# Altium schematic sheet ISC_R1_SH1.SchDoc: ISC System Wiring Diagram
size C; DrawnBy: Filiberto Clara; Engineer: Filiberto Clara; Organization: LIGO Laboratory; Address1: California Institute of Technology; Address2: Massachusetts Institute of Technology; SheetNumber: 10; SheetTotal: 39
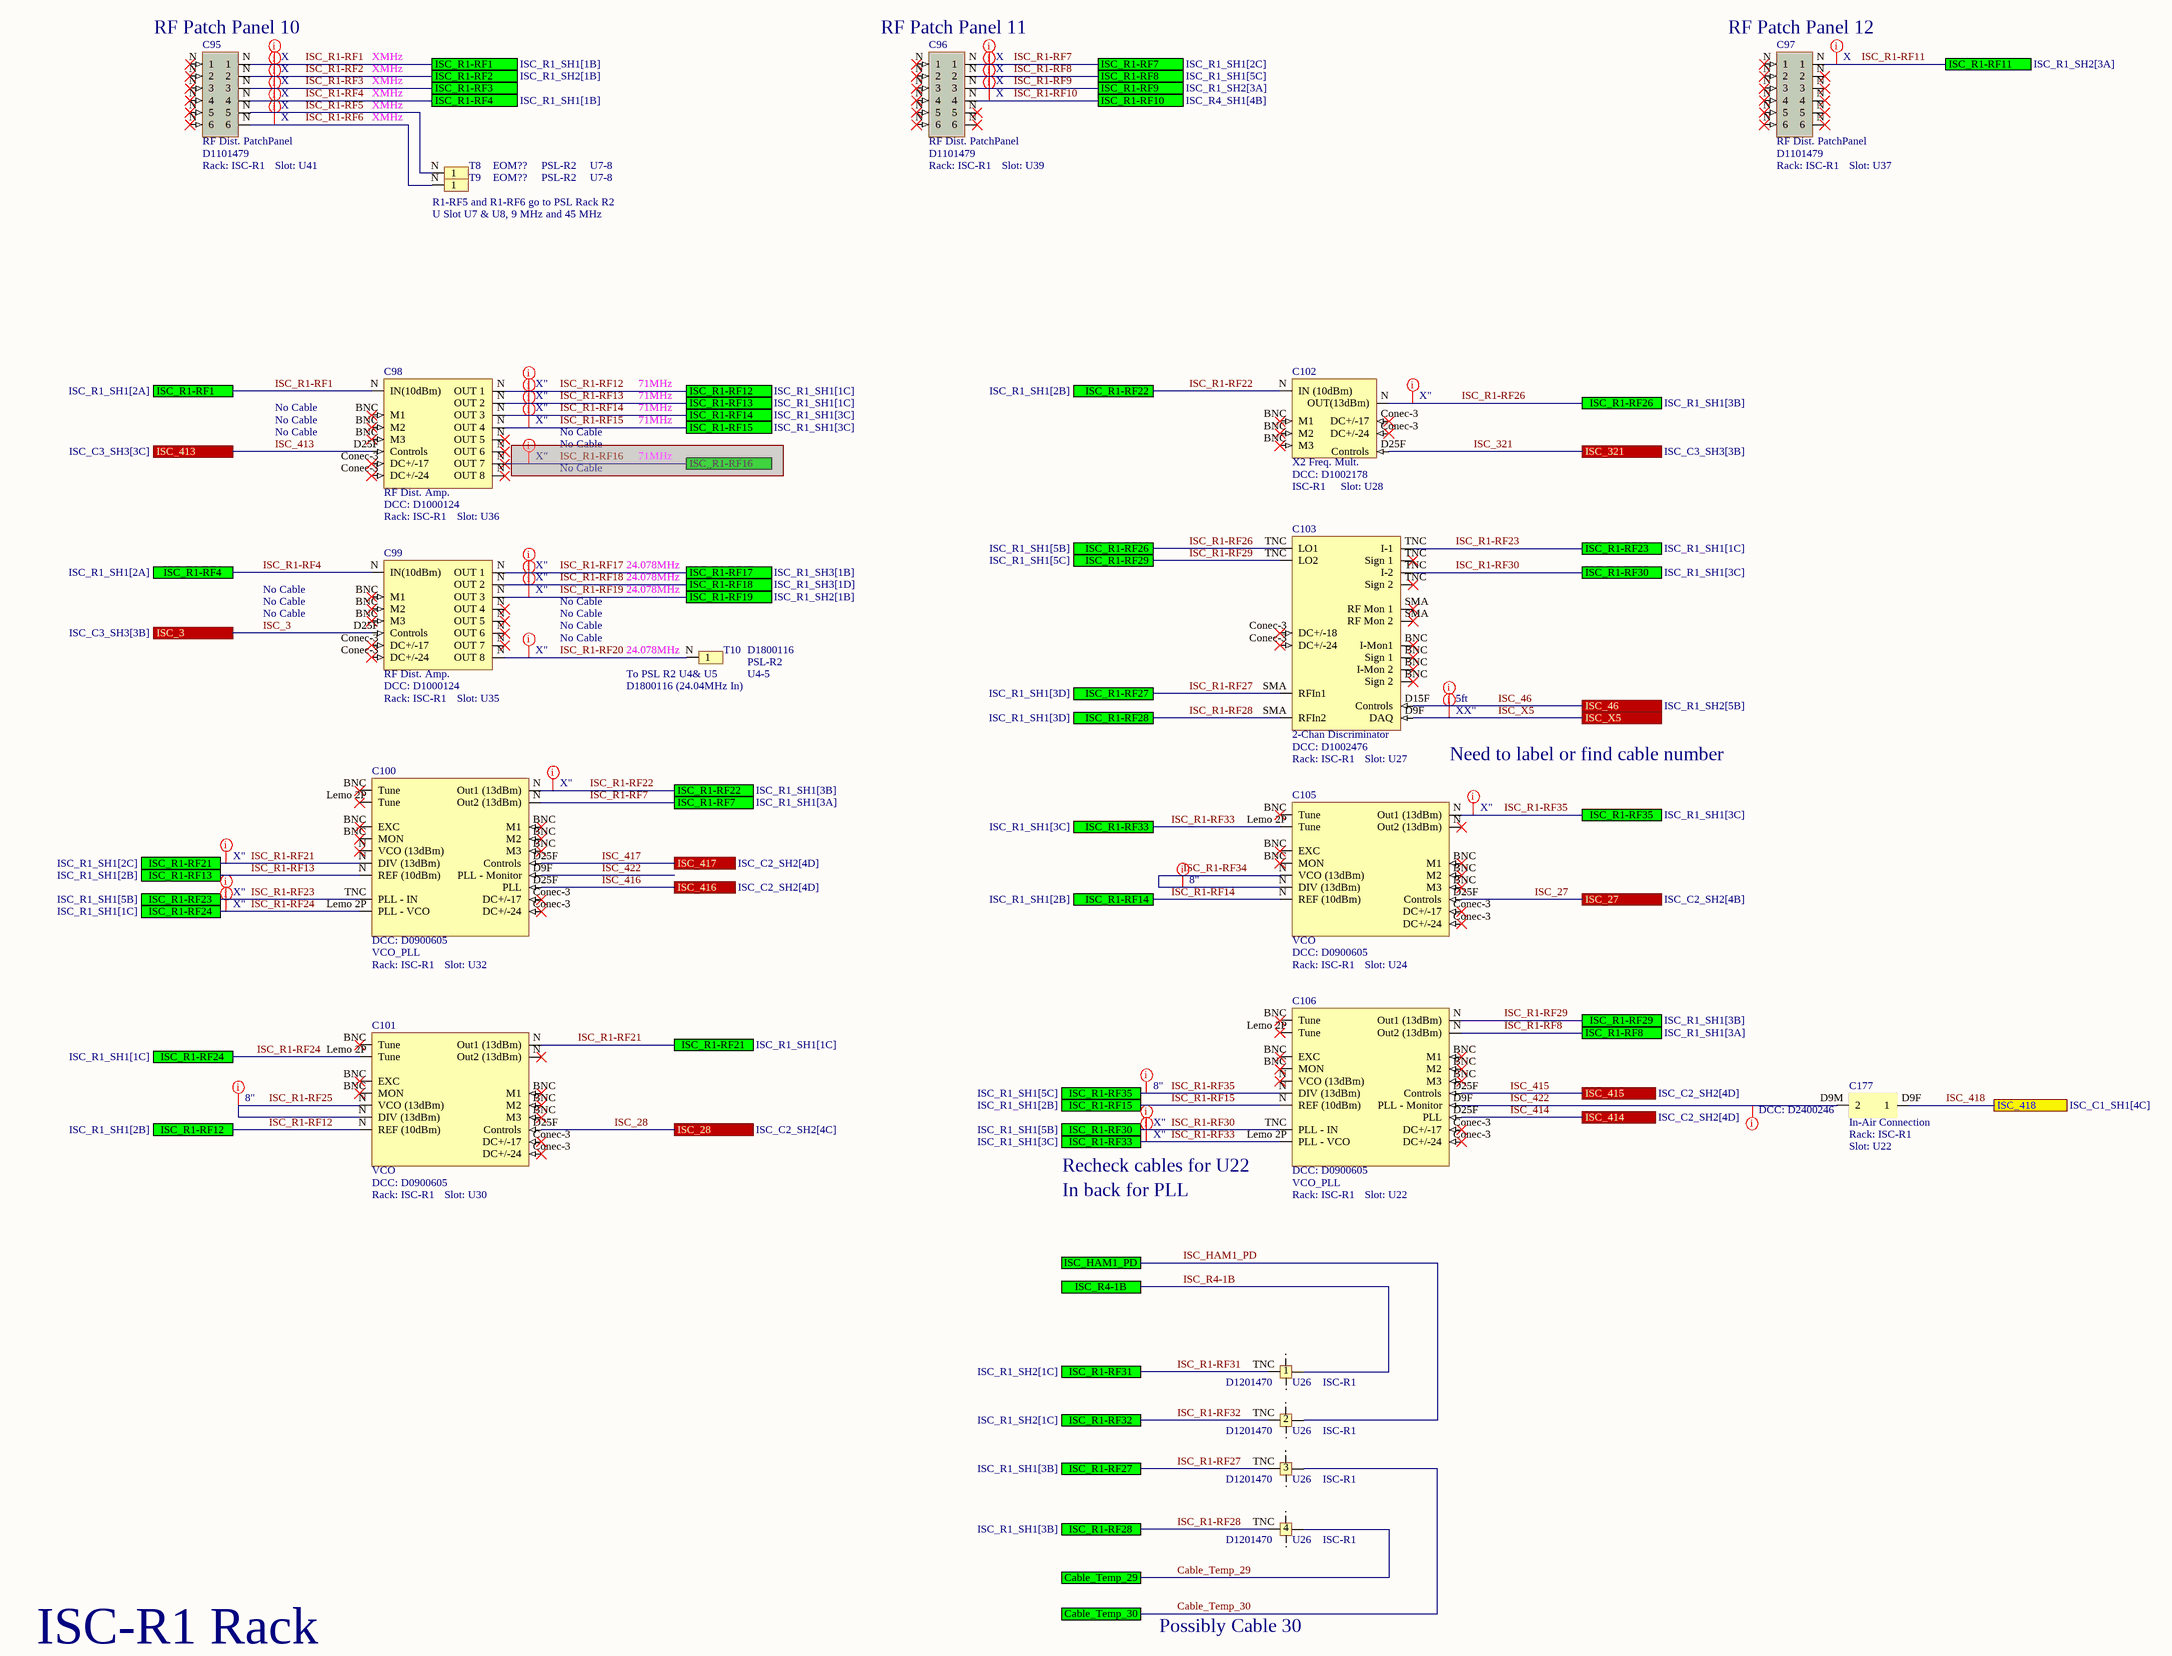
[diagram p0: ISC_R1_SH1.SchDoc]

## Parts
C95  RF Dist. PatchPanel  DCC: D1101479  Rack: ISC-R1  Slot: U41
C96  RF Dist. PatchPanel  DCC: D1101479  Rack: ISC-R1  Slot: U39
C97  RF Dist. PatchPanel  DCC: D1101479  Rack: ISC-R1  Slot: U37
C98  RF Dist. Amp.  DCC: D1000124  Rack: ISC-R1  Slot: U36
C99  RF Dist. Amp.  DCC: D1000124  Rack: ISC-R1  Slot: U35
C100  VCO_PLL  DCC: D0900605  Rack: ISC-R1  Slot: U32
C101  VCO  DCC: D0900605  Rack: ISC-R1  Slot: U30
C102  X2 Freq. Mult.  DCC: D1002178  Rack: ISC-R1  Slot: U28
C103  2-Chan Discriminator  DCC: D1002476  Rack: ISC-R1  Slot: U27
C104  DCC: D1201470  Rack: ISC-R1  Slot: U26  (hidden comment: Patch Panel TNC 1U)  (parts A,B,C,D of 4)
C105  VCO  DCC: D0900605  Rack: ISC-R1  Slot: U24
C106  VCO_PLL  DCC: D0900605  Rack: ISC-R1  Slot: U22
C177  In-Air Connection  Rack: ISC-R1  Slot: U22
T8  EOM??  Rack: PSL-R2  Slot: U7-8
T9  EOM??  Rack: PSL-R2  Slot: U7-8
T10  D1800116  Rack: PSL-R2  Slot: U4-5

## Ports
Cable_Temp_29, Cable_Temp_30, ISC_3 (see ISC_C3_SH3[3B]), ISC_27 (see ISC_C2_SH2[4B]), ISC_28 (see ISC_C2_SH2[4C]), ISC_46 (see ISC_R1_SH2[5B]), ISC_321 (see ISC_C3_SH3[3B]), ISC_413 (see ISC_C3_SH3[3C]), ISC_414 (see ISC_C2_SH2[4D]), ISC_415 (see ISC_C2_SH2[4D]), ISC_416 (see ISC_C2_SH2[4D]), ISC_417 (see ISC_C2_SH2[4D]), ISC_418 (see ISC_C1_SH1[4C]), ISC_HAM1_PD, ISC_R1-RF1 (see ISC_R1_SH1[1B]), ISC_R1-RF1 (see ISC_R1_SH1[2A]), ISC_R1-RF2 (see ISC_R1_SH2[1B]), ISC_R1-RF3, ISC_R1-RF4 (see ISC_R1_SH1[1B]), ISC_R1-RF4 (see ISC_R1_SH1[2A]), ISC_R1-RF7 (see ISC_R1_SH1[2C]), ISC_R1-RF7 (see ISC_R1_SH1[3A]), ISC_R1-RF8 (see ISC_R1_SH1[3A]), ISC_R1-RF8 (see ISC_R1_SH1[5C]), ISC_R1-RF9 (see ISC_R1_SH2[3A]), ISC_R1-RF10 (see ISC_R4_SH1[4B]), ISC_R1-RF11 (see ISC_R1_SH2[3A]), ISC_R1-RF12 (see ISC_R1_SH1[1C]), ISC_R1-RF12 (see ISC_R1_SH1[2B]), ISC_R1-RF13 (see ISC_R1_SH1[1C]), ISC_R1-RF13 (see ISC_R1_SH1[2B]), ISC_R1-RF14 (see ISC_R1_SH1[2B]), ISC_R1-RF14 (see ISC_R1_SH1[3C]), ISC_R1-RF15 (see ISC_R1_SH1[2B]), ISC_R1-RF15 (see ISC_R1_SH1[3C]), ISC_R1-RF16, ISC_R1-RF17 (see ISC_R1_SH3[1B]), ISC_R1-RF18 (see ISC_R1_SH3[1D]), ISC_R1-RF19 (see ISC_R1_SH2[1B]), ISC_R1-RF21 (see ISC_R1_SH1[1C]), ISC_R1-RF21 (see ISC_R1_SH1[2C]), ISC_R1-RF22 (see ISC_R1_SH1[2B]), ISC_R1-RF22 (see ISC_R1_SH1[3B]), ISC_R1-RF23 (see ISC_R1_SH1[1C]), ISC_R1-RF23 (see ISC_R1_SH1[5B]), ISC_R1-RF24 (see ISC_R1_SH1[1C]), ISC_R1-RF26 (see ISC_R1_SH1[3B]), ISC_R1-RF26 (see ISC_R1_SH1[5B]), ISC_R1-RF27 (see ISC_R1_SH1[3B]), ISC_R1-RF27 (see ISC_R1_SH1[3D]), ISC_R1-RF28 (see ISC_R1_SH1[3B]), ISC_R1-RF28 (see ISC_R1_SH1[3D]), ISC_R1-RF29 (see ISC_R1_SH1[3B]), ISC_R1-RF29 (see ISC_R1_SH1[5C]), ISC_R1-RF30 (see ISC_R1_SH1[3C]), ISC_R1-RF30 (see ISC_R1_SH1[5B]), ISC_R1-RF31 (see ISC_R1_SH2[1C]), ISC_R1-RF32 (see ISC_R1_SH2[1C]), ISC_R1-RF33 (see ISC_R1_SH1[3C]), ISC_R1-RF35 (see ISC_R1_SH1[3C]), ISC_R1-RF35 (see ISC_R1_SH1[5C]), ISC_R4-1B, ISC_X5

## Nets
Cable_Temp_29: C104.TNC ; port Cable_Temp_29
Cable_Temp_30: C104.TNC ; port Cable_Temp_30
ISC_3: C99.D25F(Controls) ; port ISC_3
ISC_27: C105.D25F(Controls) ; port ISC_27
ISC_28: C101.D25F(Controls) ; port ISC_28
ISC_46: C103.D15F(Controls) ; port ISC_46
ISC_321: C102.D25F(Controls) ; port ISC_321
ISC_413: C98.D25F(Controls) ; port ISC_413
ISC_414: C106.D25F(PLL) ; port ISC_414
ISC_415: C106.D25F(Controls) ; port ISC_415
ISC_416: C100.D25F(PLL) ; port ISC_416
ISC_417: C100.D25F(Controls) ; port ISC_417
ISC_418: C177.D9F(1) ; port ISC_418
ISC_422: C100.D9F(PLL_-_Monitor) C106.D9F(PLL_-_Monitor) C177.D9M(2)
ISC_HAM1_PD: C104.TNC ; port ISC_HAM1_PD
ISC_R1-RF1: C95.N(1) C98.N(IN(10dBm)) ; port ISC_R1-RF1
ISC_R1-RF2: C95.N(2) ; port ISC_R1-RF2
ISC_R1-RF3: C95.N(3) ; port ISC_R1-RF3
ISC_R1-RF4: C95.N(4) C99.N(IN(10dBm)) ; port ISC_R1-RF4
ISC_R1-RF5: C95.N(5) T8.N(1)
ISC_R1-RF6: C95.N(6) T9.N(1)
ISC_R1-RF7: C96.N(1) C100.N(Out2_(13dBm)) ; port ISC_R1-RF7
ISC_R1-RF8: C96.N(2) C106.N(Out2_(13dBm)) ; port ISC_R1-RF8
ISC_R1-RF9: C96.N(3) ; port ISC_R1-RF9
ISC_R1-RF10: C96.N(4) ; port ISC_R1-RF10
ISC_R1-RF11: C97.N(1) ; port ISC_R1-RF11
ISC_R1-RF12: C98.N(OUT_1) C101.N(REF_(10dBm)) ; port ISC_R1-RF12
ISC_R1-RF13: C98.N(OUT_2) C100.N(REF_(10dBm)) ; port ISC_R1-RF13
ISC_R1-RF14: C98.N(OUT_3) C105.N(REF_(10dBm)) ; port ISC_R1-RF14
ISC_R1-RF15: C98.N(OUT_4) C106.N(REF_(10dBm)) ; port ISC_R1-RF15
ISC_R1-RF17: C99.N(OUT_1) ; port ISC_R1-RF17
ISC_R1-RF18: C99.N(OUT_2) ; port ISC_R1-RF18
ISC_R1-RF19: C99.N(OUT_3) ; port ISC_R1-RF19
ISC_R1-RF20: C99.N(OUT_8) T10.N(1)
ISC_R1-RF21: C100.N(VCO_(13dBm)) C101.N(Out1_(13dBm)) ; port ISC_R1-RF21
ISC_R1-RF22: C100.N(Out1_(13dBm)) C102.N(IN_(10dBm)) ; port ISC_R1-RF22
ISC_R1-RF23: C100.TNC(PLL_-_IN) C103.TNC(I-1) ; port ISC_R1-RF23
ISC_R1-RF24: C100.Lemo_2P(Tune) C101.Lemo_2P(Tune) ; port ISC_R1-RF24
ISC_R1-RF25: C101.N(VCO_(13dBm))
ISC_R1-RF26: C102.N(OUT(13dBm)) C103.TNC(LO1) ; port ISC_R1-RF26
ISC_R1-RF27: C103.SMA(RF_Mon_1) C104.TNC ; port ISC_R1-RF27
ISC_R1-RF28: C103.SMA(RFIn2) C104.TNC ; port ISC_R1-RF28
ISC_R1-RF29: C103.TNC(LO2) C106.N(Out1_(13dBm)) ; port ISC_R1-RF29
ISC_R1-RF30: C103.TNC(I-2) C106.TNC(PLL_-_IN) ; port ISC_R1-RF30
ISC_R1-RF31: C104.TNC ; port ISC_R1-RF31
ISC_R1-RF32: C104.TNC ; port ISC_R1-RF32
ISC_R1-RF33: C105.Lemo_2P(Tune) C106.Lemo_2P(Tune) ; port ISC_R1-RF33
ISC_R1-RF34: C105.N(VCO_(13dBm))
ISC_R1-RF35: C105.N(Out1_(13dBm)) C106.N(VCO_(13dBm)) ; port ISC_R1-RF35
ISC_R4-1B: C104.TNC ; port ISC_R4-1B
ISC_X5: C103.D9F(DAQ) ; port ISC_X5

Not connected (* = marked no-connect by the designer): C98 BNC(M1)* Conec-3(DC+/-17)*; C99 BNC(M1)* Conec-3(DC+/-17)*; C100 BNC(Tune)* Conec-3(DC+/-17)*; C101 BNC(Tune)* Conec-3(DC+/-17)*; C102 BNC(M1)* Conec-3(DC+/-17)*; C103 BNC(I-Mon1)* Conec-3(DC+/-18)*; C105 BNC(Tune)* Conec-3(DC+/-17)*; C106 BNC(Tune)* Conec-3(DC+/-17)*

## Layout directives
Length: X": ISC_R1-RF12, ISC_R1-RF13, ISC_R1-RF14, ISC_R1-RF15, ISC_R1-RF17, ISC_R1-RF18, ISC_R1-RF19, ISC_R1-RF20, ISC_R1-RF21, ISC_R1-RF22, ISC_R1-RF23, ISC_R1-RF24, ISC_R1-RF26, ISC_R1-RF30, ISC_R1-RF33, ISC_R1-RF35
Length: X: ISC_R1-RF1, ISC_R1-RF2, ISC_R1-RF3, ISC_R1-RF4, ISC_R1-RF5, ISC_R1-RF6, ISC_R1-RF7, ISC_R1-RF8, ISC_R1-RF9, ISC_R1-RF10, ISC_R1-RF11
Length: 5ft: ISC_46
Length: XX": ISC_X5
Length: 8": ISC_R1-RF25, ISC_R1-RF34, ISC_R1-RF35
DCC: D2400246: ISC_422

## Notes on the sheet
- (near C95) RF Patch Panel 10
- (near C96) RF Patch Panel 11
- (near C97) RF Patch Panel 12
- XMHz
- (near T9) R1-RF5 and R1-RF6 go to PSL Rack R2
- U Slot U7 & U8, 9 MHz and 45 MHz
- 71MHz
- No Cable
- 24.078MHz
- (near T10) 24.078MHz
- (near T10) To PSL R2 U4& U5
- (near T10) D1800116 (24.04MHz In)
- Need to label or find cable number
- (near C106) Recheck cables for U22
- In back for PLL
- ISC-R1 Rack
- Possibly Cable 30

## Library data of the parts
C95-C97 = RF Dist. PatchPanel: Serial: Sxxxxxxx; System: ISC
C98 C99 = RF Distribution Amplifier: Serial: Sxxxxxxx; System: ISC
C100 C106 = VCO_PLL: Serial: Sxxxxxxx; System: ISC
C101 C105 = VCO: Serial: Sxxxxxxx; System: ISC
C102 = X2 Freq. Mult.: Serial: Sxxxxxxx; System: ISC
C103 = 2-Chan Discriminator: Serial: Sxxxxxxx; System: ISC
C104 = Patch Panel TNC 1U: Patch Panel (D1201470); Serial: Sxxxxxxx; System: ISC
C177 = InAirConnectionDB9: Serial: Sxxxxxxx; System: ISC
T8-T10 = Placeholder: IO Chassis; Serial: Sxxxxxxx; System: ISC; DCC: tbd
